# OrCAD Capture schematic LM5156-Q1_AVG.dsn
size D; title: LM5156x-Q1 2.2-MHz Wide VIN 65-V Nonsynchronous Boost/SEPIC/; rev: 1.0; note: Datasheet: SNVSBI7B     EVM: SNVU696; note: Synchronous Step Down Converter
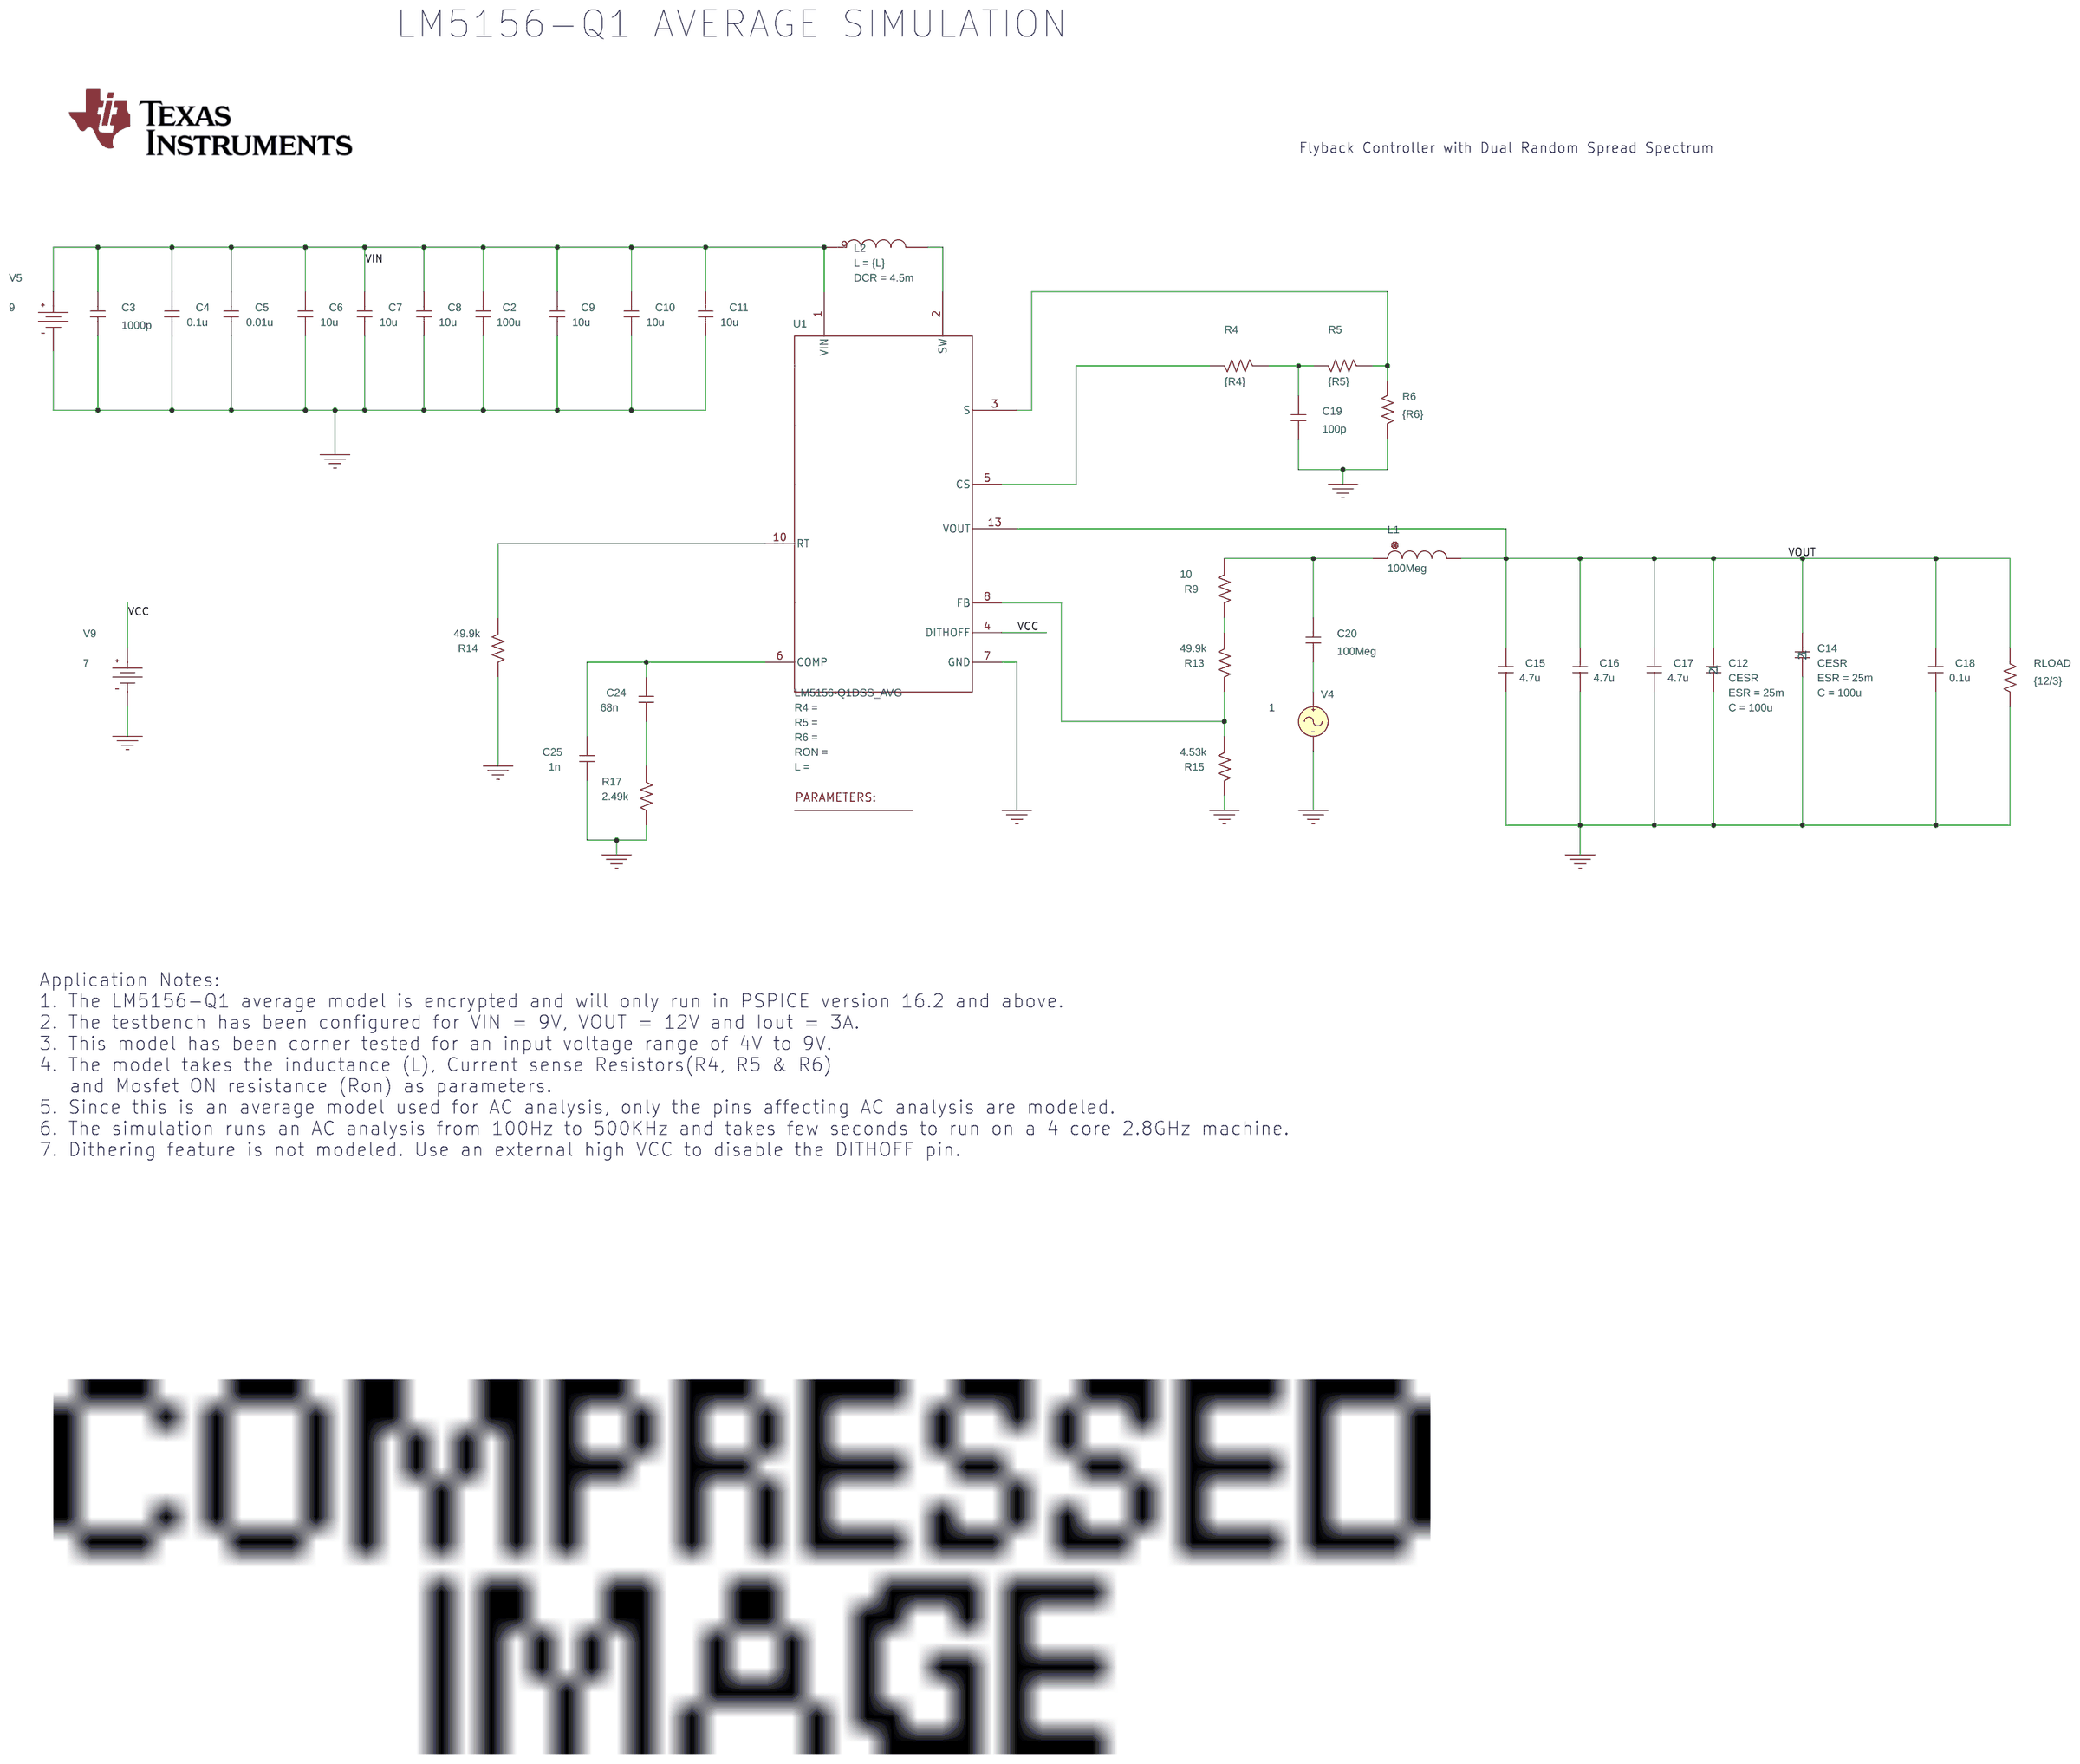
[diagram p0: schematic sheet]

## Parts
1  PARAM
C2  100u  [RAD/CK05]
C3  1000p  [RAD/CK05]
C4  0.1u  [RAD/CK05]
C5  0.01u  [RAD/CK05]
C6  10u  [RAD/CK05]
C7  10u  [RAD/CK05]
C8  10u  [RAD/CK05]
C9  10u  [RAD/CK05]
C10  10u  [RAD/CK05]
C11  10u  [RAD/CK05]
C12  CESR
C14  CESR
C15  4.7u  [RAD/CK05]
C16  4.7u  [RAD/CK05]
C17  4.7u  [RAD/CK05]
C18  0.1u  [RAD/CK05]
C19  100p  [RAD/CK05]
C20  100Meg  [RAD/CK05]
C24  68n  [RAD/CK05]
C25  1n  [RAD/CK05]
L1  100Meg  [DISC/.350x.175/LS.200x.100/.034]
L2  LDCR
R4  {R4}  [AX/RC05]
R5  {R5}  [AX/RC05]
R6  {R6}  [AX/RC05]
R9  10  [AX/RC05]
R13  49.9k  [AX/RC05]
R14  49.9k  [AX/RC05]
R15  4.53k  [AX/RC05]
R17  2.49k  [AX/RC05]
RLOAD  {12/3}  [AX/RC05]
U1  LM5156-Q1DSS_AVG  [DSS0012C]
V4  VAC
V5  VDC
V9  VDC

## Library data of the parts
1 = PARAM: L: 2.2u; R4: 1u; R5: 100; R6: 0.004; Ron: 5.1m
C2-C11 C15-C20 C24 C25 = C
C12 = CESR: C: 100u; ESR: 25m; PSpiceTemplate: X^@REFDES %1 %2 @MODEL PARAMS: ?C|C=@C||C=10U| ?ESR|ESR=@ESR||ESR=2M|
C14 = CESR_1: C: 100u; ESR: 25m; PSpiceTemplate: X^@REFDES %1 %2 @MODEL PARAMS: ?C|C=@C||C=10U| ?ESR|ESR=@ESR||ESR=2M|
L1 = L
L2 = LDCR_0: DCR: 4.5m; L: {L}; PSpiceTemplate: X^@REFDES %IN %OUT @MODEL PARAMS:  ?L|L=@L||L=1u|  ?DCR|DCR=@DCR||DCR=0.01|
R4-R6 R9 R13-R15 R17 RLOAD = R
U1 = LM5156-Q1DSS_AVG
V4 = VAC: ACMAG: 1; ACPHASE: 0
V5 = VDC: DC: 9
V9 = VDC: DC: 7

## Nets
VCC: U1.4(DITHOFF) V9.0(+)
VIN: C2.1 C3.1 C4.1 C5.1 C6.1 C7.1 C8.1 C9.1 C10.1 C11.1 L2.1(IN) U1.1(VIN) V5.0(+)
0: C2.2 C3.2 C4.2 C5.2 C6.2 C7.2 C8.2 C9.2 C10.2 C11.2 C12.2 C14.2 C15.2 C16.2 C17.2 C18.2 C19.2 C25.2 R6.1 R14.2 R15.2 R17.2 RLOAD.2 U1.7(GND) V4.2(-) V5.1(-) V9.1(-)
VOUT: C12.1 C14.1 C15.1 C16.1 C17.1 C18.1 L1.2 RLOAD.1 U1.13(VOUT)
N16770483: C20.1 L1.1 R9.1
N16770581: R13.2 R15.1 U1.8(FB)
N16770593: C20.2 V4.1(+)
N16770707: R9.2 R13.1
N16771591: R4.2 U1.5(CS)
N16771595: C19.1 R4.1 R5.2
N16771677: R5.1 R6.2 U1.3(S)
N16775899: L2.3(OUT) U1.2(SW)
N16781250: R14.1 U1.10(RT)
N16781617: C24.2 R17.1
N16781620: C24.1 C25.1 U1.6(COMP)

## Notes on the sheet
- LM5156-Q1 AVERAGE SIMULATION
- Flyback Controller with Dual Random Spread Spectrum
- Application Notes:
  1. The LM5156-Q1 average model is encrypted and will only run in PSPICE version 16.2 and above.
  2. The testbench has been configured for VIN = 9V, VOUT = 12V and Iout = 3A.
  3. This model has been corner tested for an input voltage range of 4V to 9V.
  4. The model takes the inductance (L), Current sense Resistors(R4, R5 & R6)
     and Mosfet ON resistance (Ron) as parameters.
  5. Since this is an average model used for AC analysis, only the pins affecting AC analysis are modeled.
  6. The simulation runs an AC analysis from 100Hz to 500KHz and takes few seconds to run on a 4 core 2.8GHz machine.
  7. Dithering feature is not modeled. Use an external high VCC to disable the DITHOFF pin.
